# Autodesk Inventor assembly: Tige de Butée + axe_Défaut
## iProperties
Shininess: 64.0
Length Units: 11269
Angle Units: 11279
Time Units: 11290
Mass Units: 11283
Length Display Precision: 3
Angle Display Precision: 2
Compacted: True
Created: 2006-11
Part Number: Tige de Butée + axe_Défaut
Document SubType Name: Assembly
Designer: profs_sti
Density: 0.0
Volumn: 0.0
Area: 0.0
PropertySet Name: Model Information
Control State: 0
Master: False
Checked Out: False
Author: profs_sti
